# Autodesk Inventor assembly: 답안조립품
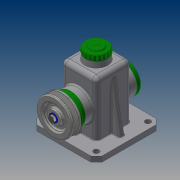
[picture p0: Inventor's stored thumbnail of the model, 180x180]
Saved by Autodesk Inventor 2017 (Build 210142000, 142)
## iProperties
Part Number: 답안조립품
Material: 일반
Document SubType Name: Assembly
Designer: 20
Author: 20
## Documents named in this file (13)
- C:\Users\20\Desktop\470818V1013\답안조립품.iam
- C:\Users\20\Desktop\470818V1013\본체.ipt
- C:\Users\20\Desktop\470818V1013\축.ipt
- C:\Users\20\Desktop\470818V1013\키 5 x 5 x 14.ipt
- C:\Users\20\Desktop\470818V1013\앞커버.ipt
- C:\Users\20\Desktop\470818V1013\오일실 15 25 7.ipt
- C:\Users\20\Desktop\470818V1013\베어링 15 x 35 x 11.ipt
- C:\Users\20\Desktop\470818V1013\멈춤링 15 x 1.ipt
- C:\Users\20\Desktop\470818V1013\뒤커버.ipt
- C:\Users\20\Desktop\470818V1013\상부캡.ipt
- C:\Users\20\Desktop\470818V1013\V-벨트풀리.ipt
- C:\Users\20\Desktop\470818V1013\볼트 M6 x 12.ipt
- C:\Users\20\Desktop\470818V1013\와셔.ipt
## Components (1 placed, 1 different names)
1. V-벨트풀리:1
